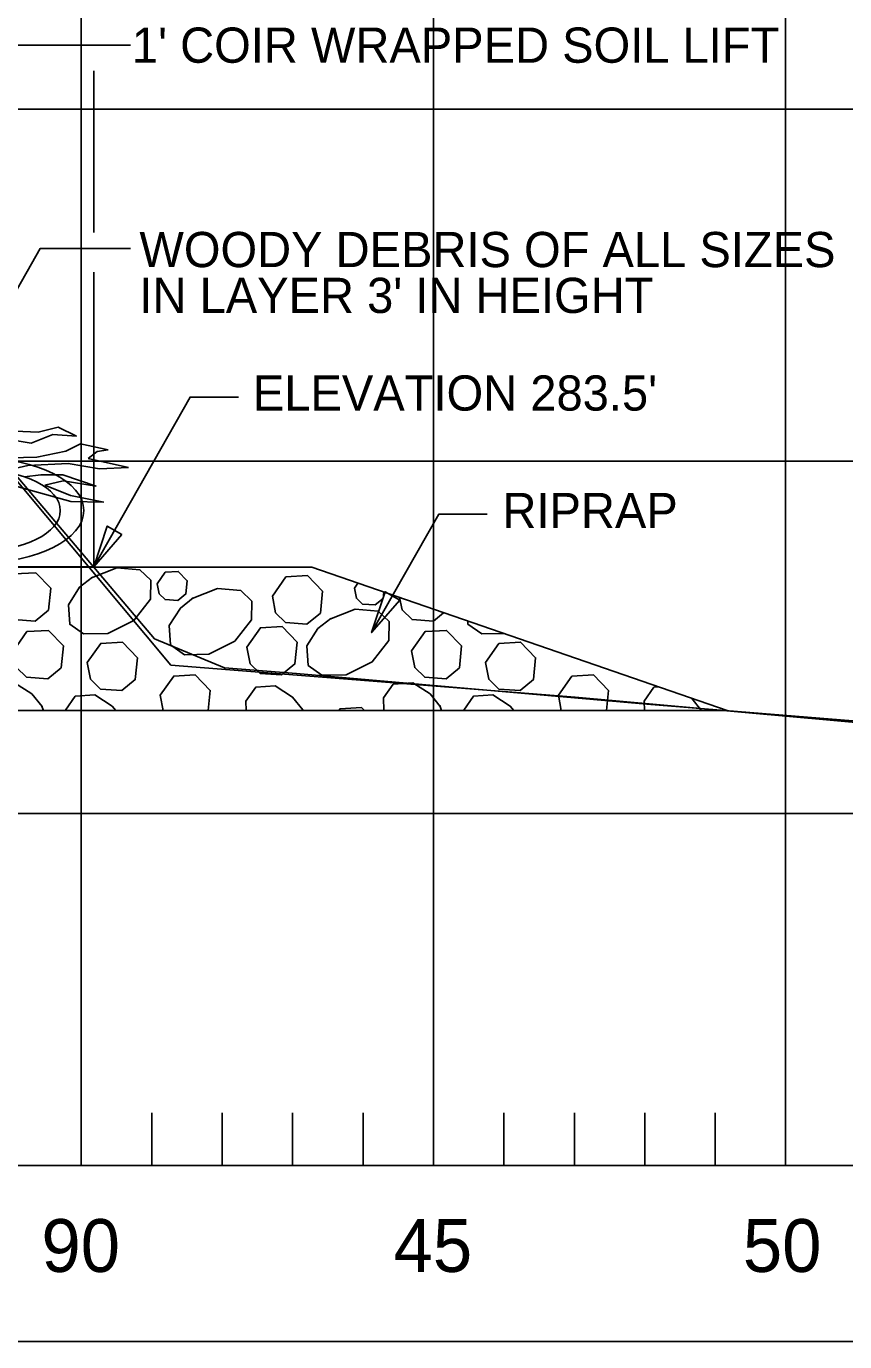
# Model space of a CAD drawing. Extents: x 1578769 to 1579225, y 724002 to 724828.
# Drawn here: x 1578879.25 to 1578890.87, y 724384.65 to 724403.32 of the extents above; entities that cross this region are included whole.
import ezdxf

# ---------------------------------------------------------------- set-up
doc = ezdxf.new("R2010")
doc.units = 0
for name, color, linetype in [('1', 7, 'Continuous'), ('Default', 7, 'Continuous'), ('Old_Level_1', 7, 'Continuous'), ('Old_Level_41', 7, 'Continuous'), ('Old_Level_42', 7, 'Continuous'), ('R_Exist Surface', 7, 'Continuous'), ('R_Fin Surface', 7, 'Continuous'), ('R_Rip-Rap', 7, 'Continuous')]:
    doc.layers.add(name, color=color, linetype=linetype)

msp = doc.modelspace()

# ---------------------------------------------------------------- linework, layer by layer
at = {"layer": '1'}
for p, q in [((1578880.209, 724400.393), (1578880.209, 724402.691)), ((1578880.209, 724395.646), (1578880.209, 724399.834))]:
    msp.add_line(p, q, dxfattribs=at)
for points in [[(1578876.67, 724399.617), (1578878.619, 724403.056), (1578880.73, 724403.056)], [(1578877.83, 724397.313), (1578879.448, 724400.168), (1578880.73, 724400.168)], [(1578880.209, 724395.646), (1578881.577, 724398.059), (1578882.262, 724398.059)], [(1578884.154, 724394.713), (1578885.109, 724396.396), (1578885.794, 724396.396)]]:
    msp.add_lwpolyline(points, dxfattribs=at)
for points in [[(1578880.609, 724396.108), (1578880.209, 724395.646), (1578880.4, 724396.227)], [(1578884.554, 724395.175), (1578884.154, 724394.713), (1578884.345, 724395.294)]]:
    msp.add_lwpolyline(points, close=True, dxfattribs=at)
at = {"layer": 'Default'}
msp.add_line((1578840.032, 724387.146), (1579140.032, 724387.146), dxfattribs=at)
msp.add_lwpolyline([(1578840.032, 724407.278), (1578843.972, 724407.183), (1578868.722, 724406.957), (1578870.692, 724406.938), (1578871.022, 724406.546), (1578881.302, 724394.253), (1578887.042, 724393.796), (1578904.532, 724392.22), (1578918.752, 724390.976), (1578924.862, 724390.388), (1578951.062, 724393.135), (1578979.152, 724396.133), (1578991.892, 724397.482), (1578996.872, 724398.009), (1579008.382, 724399.253), (1579066.252, 724403.439), (1579074.562, 724404.146)], dxfattribs=at)
at = {"layer": 'Old_Level_1'}
for p, q in [((1578879.418, 724397.56), (1578879.702, 724397.633)), ((1578879.702, 724397.633), (1578879.966, 724397.504)), ((1578879.318, 724397.406), (1578878.822, 724397.487)), ((1578878.872, 724397.582), (1578879.418, 724397.56)), ((1578879.627, 724397.526), (1578879.318, 724397.406)), ((1578879.966, 724397.504), (1578879.627, 724397.526)), ((1578879.4, 724397.203), (1578879.814, 724397.289)), ((1578879.814, 724397.289), (1578880.021, 724397.393)), ((1578880.021, 724397.393), (1578880.412, 724397.311)), ((1578880.256, 724397.286), (1578880.129, 724397.186)), ((1578880.412, 724397.311), (1578880.256, 724397.286)), ((1578878.75, 724397.19), (1578879.4, 724397.203)), ((1578879.272, 724397.087), (1578878.884, 724396.997)), ((1578879.844, 724397.113), (1578879.272, 724397.087)), ((1578880.288, 724397.04), (1578879.844, 724397.113)), ((1578880.129, 724397.186), (1578880.704, 724397.058)), ((1578879.224, 724396.924), (1578879.458, 724396.954)), ((1578879.458, 724396.954), (1578879.77, 724396.954)), ((1578879.77, 724396.954), (1578880.241, 724396.791)), ((1578880.704, 724397.058), (1578880.288, 724397.04)), ((1578879.882, 724396.576), (1578878.966, 724396.829)), ((1578879.772, 724396.868), (1578879.513, 724396.808)), ((1578879.513, 724396.808), (1578879.88, 724396.661)), ((1578880.241, 724396.791), (1578879.772, 724396.868)), ((1578879.88, 724396.661), (1578880.35, 724396.567)), ((1578880.35, 724396.567), (1578879.882, 724396.576))]:
    msp.add_line(p, q, dxfattribs=at)
msp.add_lwpolyline([(1578815.032, 724419.646), (1578942.532, 724419.646), (1578942.532, 724384.646), (1578815.032, 724384.646)], close=True, dxfattribs=at)
msp.add_lwpolyline([(1578820.032, 724417.146), (1578940.032, 724417.146), (1578940.032, 724387.146), (1578820.032, 724387.146)], dxfattribs=at)
for major_axis in [(1.486, 0), (1.152, 0)]:
    msp.add_ellipse((1578878.582, 724396.447), major_axis=major_axis, ratio=0.5, dxfattribs=at)
at = {"layer": 'Old_Level_41'}
for p, q in [((1578880.032, 724387.146), (1578880.032, 724417.146)), ((1578885.032, 724387.146), (1578885.032, 724417.146)), ((1578890.032, 724417.146), (1578890.032, 724387.146))]:
    msp.add_line(p, q, dxfattribs=at)
for points in [[(1578820.032, 724402.146), (1578940.032, 724402.146)], [(1578940.032, 724397.146), (1578820.032, 724397.146)], [(1578820.032, 724392.146), (1578940.032, 724392.146)]]:
    msp.add_lwpolyline(points, dxfattribs=at)
at = {"layer": 'Old_Level_42'}
for p, q in [((1578881.032, 724387.896), (1578881.032, 724387.146)), ((1578882.032, 724387.896), (1578882.032, 724387.146)), ((1578883.032, 724387.896), (1578883.032, 724387.146)), ((1578884.032, 724387.896), (1578884.032, 724387.146)), ((1578886.032, 724387.896), (1578886.032, 724387.146)), ((1578887.032, 724387.896), (1578887.032, 724387.146)), ((1578888.032, 724387.896), (1578888.032, 724387.146)), ((1578889.032, 724387.896), (1578889.032, 724387.146))]:
    msp.add_line(p, q, dxfattribs=at)
at = {"layer": 'R_Exist Surface'}
msp.add_lwpolyline([(1578820.032, 724407.308), (1578840.086, 724407.296), (1578856.158, 724407.113), (1578866.051, 724406.984), (1578870.101, 724406.953), (1578871.119, 724406.484), (1578874.093, 724402.856), (1578881.072, 724394.627), (1578882.067, 724394.215), (1578883.085, 724394.135), (1578888.061, 724393.7), (1578893.092, 724393.289), (1578898.075, 724392.849), (1578907.062, 724392.008), (1578915.073, 724391.301), (1578925.131, 724390.401), (1578931.075, 724391.042), (1578938.041, 724391.763), (1578940.032, 724391.965)], dxfattribs=at)
at = {"layer": 'R_Fin Surface'}
msp.add_lwpolyline([(1578866.541, 724395.646), (1578880.209, 724395.646)], dxfattribs=at)
msp.add_lwpolyline([(1578866.541, 724395.646), (1578880.209, 724395.646)], dxfattribs=at)
at = {"layer": 'R_Rip-Rap'}
for p, q in [((1578876.034, 724395.641), (1578883.305, 724395.641)), ((1578883.305, 724395.641), (1578889.2, 724393.607)), ((1578883.91, 724395.344), (1578883.96, 724395.415)), ((1578881.194, 724393.607), (1578881.152, 724393.824)), ((1578886.847, 724393.607), (1578886.805, 724393.824)), ((1578888.7, 724393.78), (1578888.83, 724393.616)), ((1578889.2, 724393.607), (1578876.034, 724393.607)), ((1578879.467, 724393.677), (1578879.494, 724393.607)), ((1578883.168, 724393.631), (1578883.177, 724393.607)), ((1578885.12, 724393.677), (1578885.148, 724393.607)), ((1578888.821, 724393.631), (1578888.83, 724393.607))]:
    msp.add_line(p, q, dxfattribs=at)
for points in [[(1578880.175, 724395.492), (1578880.534, 724395.634), (1578880.864, 724395.606), (1578881.021, 724395.457), (1578881.016, 724395.189), (1578880.778, 724394.885), (1578880.41, 724394.701), (1578880.063, 724394.695), (1578879.868, 724394.833), (1578879.85, 724395.109), (1578880.008, 724395.357), (1578880.19, 724395.501)], [(1578881.109, 724395.407), (1578881.224, 724395.571), (1578881.408, 724395.582), (1578881.536, 724395.449), (1578881.518, 724395.263), (1578881.404, 724395.169), (1578881.222, 724395.182), (1578881.137, 724395.265), (1578881.109, 724395.407)], [(1578878.886, 724395.274), (1578879.078, 724395.547), (1578879.385, 724395.564), (1578879.598, 724395.343), (1578879.567, 724395.034), (1578879.378, 724394.876), (1578879.075, 724394.898), (1578878.932, 724395.036), (1578878.886, 724395.274)], [(1578882.745, 724395.232), (1578882.937, 724395.505), (1578883.243, 724395.523), (1578883.457, 724395.302), (1578883.426, 724394.992), (1578883.236, 724394.834), (1578882.933, 724394.856), (1578882.791, 724394.995), (1578882.745, 724395.232)], [(1578881.607, 724395.197), (1578881.966, 724395.339), (1578882.296, 724395.311), (1578882.453, 724395.162), (1578882.448, 724394.894), (1578882.21, 724394.59), (1578881.842, 724394.406), (1578881.495, 724394.4), (1578881.3, 724394.538), (1578881.281, 724394.814), (1578881.44, 724395.062), (1578881.621, 724395.206)], [(1578884.327, 724395.288), (1578884.319, 724395.2), (1578884.205, 724395.106), (1578884.023, 724395.119), (1578883.938, 724395.202), (1578883.91, 724395.344)], [(1578885.175, 724394.996), (1578885.031, 724394.876), (1578884.728, 724394.898), (1578884.586, 724395.036), (1578884.552, 724395.211)], [(1578883.559, 724394.907), (1578883.918, 724395.049), (1578884.248, 724395.02), (1578884.405, 724394.871), (1578884.4, 724394.603), (1578884.162, 724394.299), (1578883.794, 724394.115), (1578883.447, 724394.109), (1578883.252, 724394.248), (1578883.233, 724394.524), (1578883.392, 724394.771), (1578883.573, 724394.916)], [(1578886.033, 724394.7), (1578885.717, 724394.695), (1578885.522, 724394.833), (1578885.519, 724394.877)], [(1578879.067, 724394.456), (1578879.259, 724394.729), (1578879.566, 724394.746), (1578879.779, 724394.525), (1578879.748, 724394.216), (1578879.558, 724394.058), (1578879.256, 724394.08), (1578879.113, 724394.218), (1578879.067, 724394.456)], [(1578882.383, 724394.509), (1578882.575, 724394.782), (1578882.882, 724394.8), (1578883.095, 724394.579), (1578883.064, 724394.269), (1578882.875, 724394.112), (1578882.572, 724394.134), (1578882.43, 724394.272), (1578882.383, 724394.509)], [(1578884.72, 724394.456), (1578884.912, 724394.729), (1578885.219, 724394.746), (1578885.432, 724394.525), (1578885.401, 724394.216), (1578885.212, 724394.058), (1578884.909, 724394.08), (1578884.767, 724394.218), (1578884.72, 724394.456)], [(1578880.117, 724394.288), (1578880.309, 724394.561), (1578880.616, 724394.579), (1578880.829, 724394.358), (1578880.798, 724394.048), (1578880.609, 724393.891), (1578880.306, 724393.913), (1578880.163, 724394.051), (1578880.117, 724394.288)], [(1578885.77, 724394.288), (1578885.962, 724394.561), (1578886.269, 724394.579), (1578886.482, 724394.358), (1578886.451, 724394.048), (1578886.262, 724393.891), (1578885.959, 724393.913), (1578885.817, 724394.051), (1578885.771, 724394.288)], [(1578881.151, 724393.824), (1578881.344, 724394.097), (1578881.65, 724394.114), (1578881.863, 724393.893), (1578881.835, 724393.607)], [(1578886.805, 724393.824), (1578886.997, 724394.097), (1578887.304, 724394.114), (1578887.517, 724393.893), (1578887.488, 724393.607)], [(1578878.672, 724393.607), (1578878.669, 724393.789), (1578878.808, 724393.984), (1578879.084, 724394.002), (1578879.331, 724393.844), (1578879.476, 724393.663)], [(1578882.373, 724393.607), (1578882.37, 724393.742), (1578882.509, 724393.937), (1578882.785, 724393.956), (1578883.032, 724393.798), (1578883.177, 724393.616)], [(1578884.326, 724393.607), (1578884.322, 724393.789), (1578884.461, 724393.984), (1578884.737, 724394.002), (1578884.984, 724393.844), (1578885.129, 724393.663)], [(1578888.026, 724393.607), (1578888.024, 724393.742), (1578888.162, 724393.937), (1578888.23, 724393.942)], [(1578879.808, 724393.607), (1578879.808, 724393.614), (1578879.947, 724393.81), (1578880.223, 724393.828), (1578880.47, 724393.67), (1578880.52, 724393.607)], [(1578885.461, 724393.607), (1578885.461, 724393.614), (1578885.6, 724393.81), (1578885.876, 724393.828), (1578886.123, 724393.67), (1578886.173, 724393.607)], [(1578883.687, 724393.607), (1578883.705, 724393.632), (1578884.012, 724393.65), (1578884.052, 724393.607)]]:
    msp.add_lwpolyline(points, dxfattribs=at)

# ---------------------------------------------------------------- texts
at = {"layer": '1'}
for s, height, p in [("1' COIR WRAPPED SOIL LIFT", 0.5, (1578880.75, 724402.805)), ('WOODY DEBRIS OF ALL SIZES', 0.5, (1578880.857, 724399.903)), ("IN LAYER 3' IN HEIGHT", 0.5, (1578880.857, 724399.252)), ("ELEVATION 283.5'", 0.5, (1578882.468, 724397.866)), ('RIPRAP', 0.5, (1578886.011, 724396.197)), ('90', 0.75, (1578879.466, 724385.636)), ('45', 0.75, (1578884.466, 724385.636)), ('50', 0.75, (1578889.425, 724385.636))]:
    msp.add_text(s, height=height, dxfattribs=at).set_placement(p)

doc.saveas('drawing.dxf')
